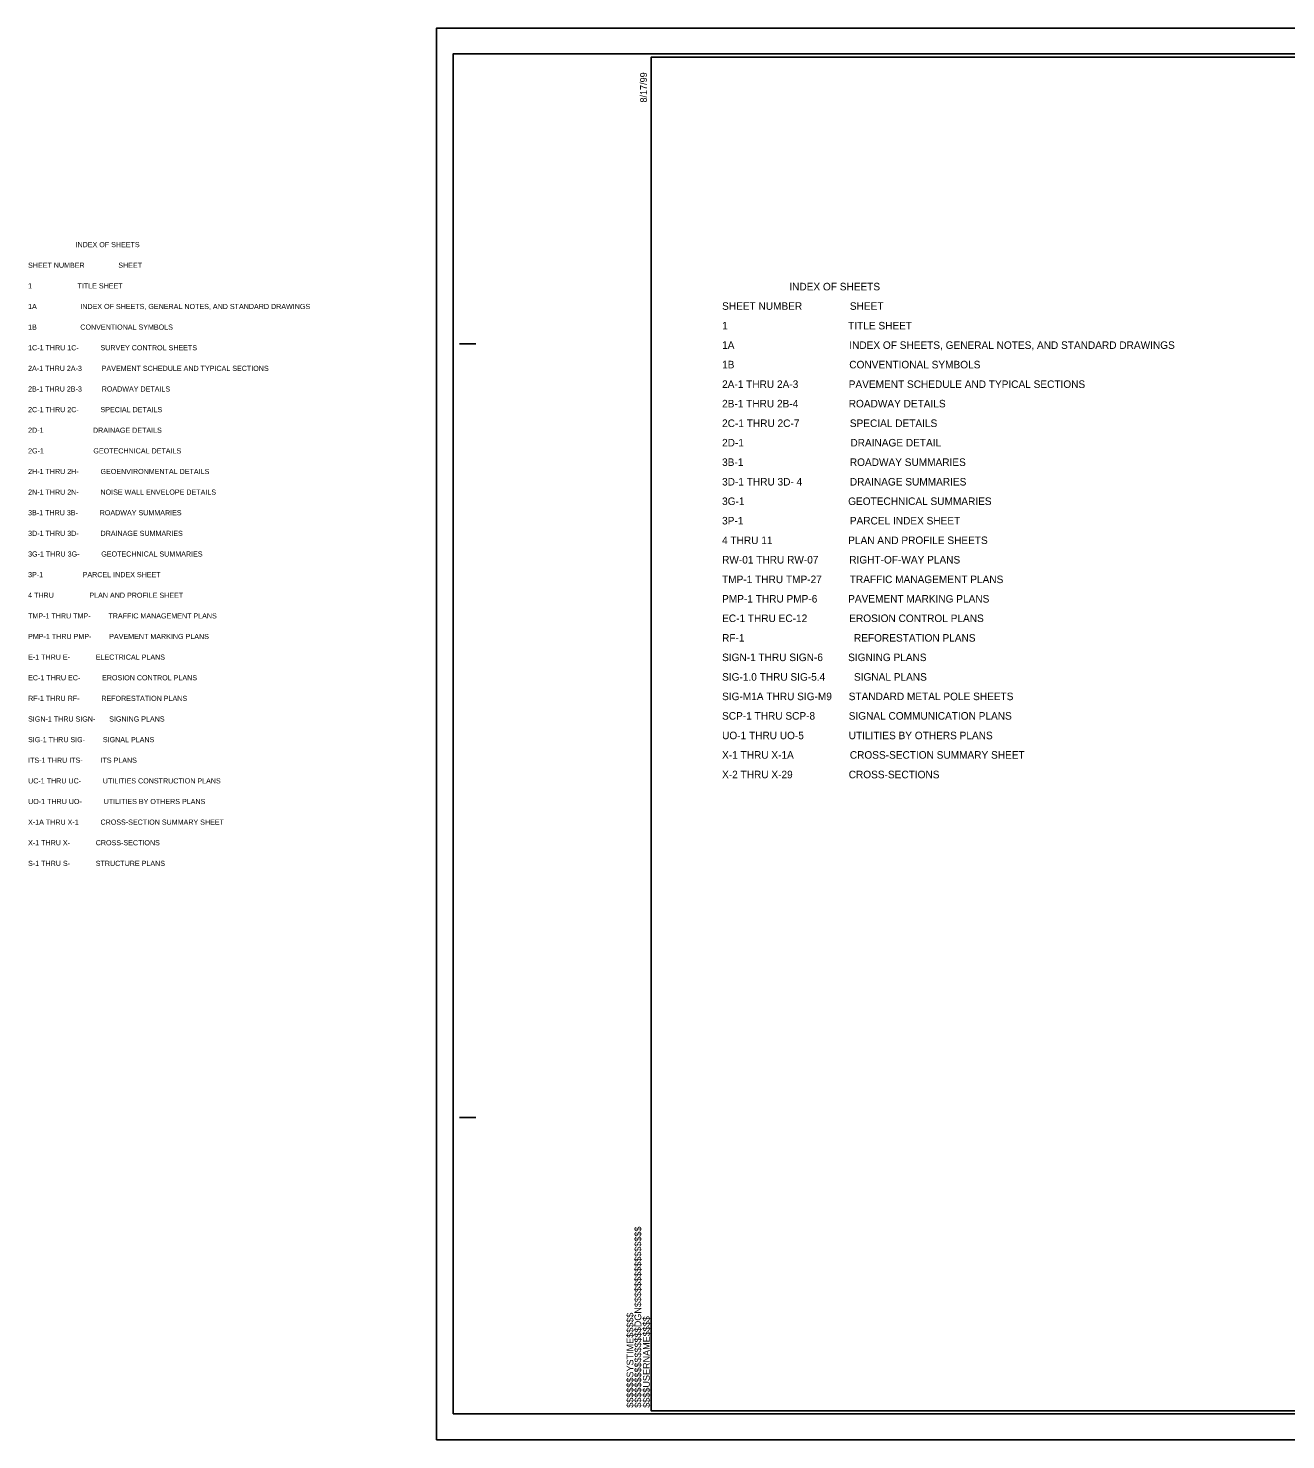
# Model space of a CAD drawing. Extents: x 3312684 to 3314684, y -677777 to -676682.
# Drawn here: x 3312684 to 3313659, y -677777 to -676682 of the extents above; entities that cross this region are included whole.
import ezdxf

# ---------------------------------------------------------------- set-up
doc = ezdxf.new("R2010")
doc.units = 0
for name, color, linetype in [('Sheet Data Text CELL', 7, 'Continuous'), ('Sheet Plan CELL', 7, 'Continuous'), ('Sheet Plot Border Inside CELL', 7, 'Continuous'), ('Sheet Plot Border Outside CELL', 7, 'Continuous')]:
    doc.layers.add(name, color=color, linetype=linetype)

msp = doc.modelspace()

# ---------------------------------------------------------------- linework, layer by layer
at = {"layer": 'Sheet Plan CELL'}
for p, q in [((3313166.7, -676704.5), (3313166.7, -676704.5)), ((3313018.2, -676927), (3313030.7, -676927)), ((3313018.2, -677527), (3313030.7, -677527)), ((3313166.7, -677754.5), (3313166.7, -677754.5))]:
    msp.add_line(p, q, dxfattribs=at)
msp.add_lwpolyline([(3314666.7, -676704.5), (3313166.7, -676704.5), (3313166.7, -677754.5), (3314666.7, -677754.5)], close=True, dxfattribs=at)
at = {"layer": 'Sheet Plot Border Inside CELL'}
msp.add_lwpolyline([(3313013.2, -677757), (3314679.2, -677757), (3314679.2, -676702), (3313013.2, -676702)], close=True, dxfattribs=at)
at = {"layer": 'Sheet Plot Border Outside CELL'}
msp.add_lwpolyline([(3313000.2, -677777), (3314683.7, -677777), (3314683.7, -676682), (3313000.2, -676682)], close=True, dxfattribs=at)

# ---------------------------------------------------------------- texts
at = {"layer": 'Sheet Data Text CELL'}
for s, height, p in [('                        INDEX OF SHEETS ', 4, (3312683.5, -676851.9)), ('SHEET NUMBER                 SHEET   ', 4, (3312683.5, -676867.9)), ('1                       TITLE SHEET', 4, (3312683.5, -676883.9)), ('                        INDEX OF SHEETS ', 5.849, (3313221.8, -676885.4)), ('1A                      INDEX OF SHEETS, GENERAL NOTES, AND STANDARD DRAWINGS', 4, (3312683.5, -676899.9)), ('SHEET NUMBER                 SHEET   ', 5.849, (3313221.8, -676900.5)), ('1B                      CONVENTIONAL SYMBOLS ', 4, (3312683.5, -676915.9)), ('1                                           TITLE SHEET', 5.849, (3313221.8, -676915.7)), ('1C-1 THRU 1C-           SURVEY CONTROL SHEETS', 4, (3312683.5, -676931.9)), ('1A                                         INDEX OF SHEETS, GENERAL NOTES, AND STANDARD DRAWINGS', 5.849, (3313221.8, -676930.8)), ('2A-1 THRU 2A-3          PAVEMENT SCHEDULE AND TYPICAL SECTIONS', 4, (3312683.5, -676947.9)), ('1B                                         CONVENTIONAL SYMBOLS ', 5.849, (3313221.8, -676945.9)), ('2B-1 THRU 2B-3          ROADWAY DETAILS ', 4, (3312683.5, -676963.9)), ('2A-1 THRU 2A-3                  PAVEMENT SCHEDULE AND TYPICAL SECTIONS', 5.849, (3313221.8, -676961.1)), ('2B-1 THRU 2B-4                  ROADWAY DETAILS ', 5.849, (3313221.8, -676976.2)), ('2C-1 THRU 2C-           SPECIAL DETAILS', 4, (3312683.5, -676979.9)), ('2D-1                         DRAINAGE DETAILS', 4, (3312683.5, -676995.9)), ('2C-1 THRU 2C-7                  SPECIAL DETAILS', 5.849, (3313221.8, -676991.4)), ('2D-1                                      DRAINAGE DETAIL', 5.849, (3313221.8, -677006.5)), ('2G-1                         GEOTECHNICAL DETAILS', 4, (3312683.5, -677011.9)), ('3B-1                                      ROADWAY SUMMARIES', 5.849, (3313221.8, -677021.6)), ('2H-1 THRU 2H-           GEOENVIRONMENTAL DETAILS', 4, (3312683.5, -677027.9)), ('3D-1 THRU 3D- 4                 DRAINAGE SUMMARIES', 5.849, (3313221.8, -677036.8)), ('2N-1 THRU 2N-           NOISE WALL ENVELOPE DETAILS', 4, (3312683.5, -677043.9)), ('3G-1                                     GEOTECHNICAL SUMMARIES', 5.849, (3313221.8, -677051.9)), ('3B-1 THRU 3B-           ROADWAY SUMMARIES', 4, (3312683.5, -677059.9)), ('3P-1                                      PARCEL INDEX SHEET', 5.849, (3313221.8, -677067)), ('3D-1 THRU 3D-           DRAINAGE SUMMARIES', 4, (3312683.5, -677075.9)), ('4 THRU 11                           PLAN AND PROFILE SHEETS', 5.849, (3313221.8, -677082.2)), ('3G-1 THRU 3G-           GEOTECHNICAL SUMMARIES', 4, (3312683.5, -677091.9)), ('RW-01 THRU RW-07           RIGHT-OF-WAY PLANS', 5.849, (3313221.8, -677097.3)), ('3P-1                    PARCEL INDEX SHEET', 4, (3312683.5, -677107.9)), ('TMP-1 THRU TMP-27          TRAFFIC MANAGEMENT PLANS', 5.849, (3313221.8, -677112.5)), ('4 THRU                  PLAN AND PROFILE SHEET', 4, (3312683.5, -677123.9)), ('PMP-1 THRU PMP-6           PAVEMENT MARKING PLANS', 5.849, (3313221.8, -677127.6)), ('TMP-1 THRU TMP-         TRAFFIC MANAGEMENT PLANS', 4, (3312683.5, -677139.9)), ('EC-1 THRU EC-12               EROSION CONTROL PLANS', 5.849, (3313221.8, -677142.7)), ('PMP-1 THRU PMP-         PAVEMENT MARKING PLANS', 4, (3312683.5, -677155.9)), ('RF-1', 5.85, (3313221.8, -677157.9)), ('    REFORESTATION PLANS', 5.849, (3313315.4, -677157.9)), ('E-1 THRU E-             ELECTRICAL PLANS', 4, (3312683.5, -677171.9)), ('SIGN-1 THRU SIGN-6         SIGNING PLANS', 5.849, (3313221.8, -677173)), ('EC-1 THRU EC-           EROSION CONTROL PLANS', 4, (3312683.5, -677187.9)), ('SIG-1.0 THRU SIG-5.4', 5.849, (3313221.8, -677188.2)), ('    SIGNAL PLANS', 5.849, (3313315.4, -677188.2)), ('RF-1 THRU RF-           REFORESTATION PLANS', 4, (3312683.5, -677203.9)), ('SIG-M1A THRU SIG-M9      STANDARD METAL POLE SHEETS', 5.849, (3313221.8, -677203.3)), ('SCP-1 THRU SCP-8            SIGNAL COMMUNICATION PLANS', 5.849, (3313221.8, -677218.4)), ('SIGN-1 THRU SIGN-       SIGNING PLANS', 4, (3312683.5, -677219.9)), ('SIG-1 THRU SIG-         SIGNAL PLANS', 4, (3312683.5, -677235.9)), ('UO-1 THRU UO-5                UTILITIES BY OTHERS PLANS', 5.849, (3313221.8, -677233.6)), ('X-1 THRU X-1A                    CROSS-SECTION SUMMARY SHEET', 5.849, (3313221.8, -677248.7)), ('ITS-1 THRU ITS-         ITS PLANS', 4, (3312683.5, -677251.9)), ('UC-1 THRU UC-           UTILITIES CONSTRUCTION PLANS', 4, (3312683.5, -677267.9)), ('X-2 THRU X-29                    CROSS-SECTIONS', 5.849, (3313221.8, -677263.9)), ('UO-1 THRU UO-           UTILITIES BY OTHERS PLANS', 4, (3312683.5, -677283.9)), ('X-1A THRU X-1           CROSS-SECTION SUMMARY SHEET', 4, (3312683.5, -677299.9)), ('X-1 THRU X-             CROSS-SECTIONS', 4, (3312683.5, -677315.9)), ('S-1 THRU S-             STRUCTURE PLANS', 4, (3312683.5, -677331.9))]:
    msp.add_text(s, height=height, dxfattribs=at).set_placement(p)
at = {"layer": 'Sheet Plan CELL'}
for s, p in [('8/17/99', (3313163.5, -676739.7)), ('$$$$$$$$$$$$$$$$DGN$$$$$$$$$$$$$$$$', (3313159.1, -677752.2)), ('$$$$$$SYSTIME$$$$$', (3313153, -677752.2)), ('$$$$USERNAME$$$$', (3313165.7, -677752.2))]:
    msp.add_text(s, height=5.25, rotation=90, dxfattribs=at).set_placement(p)

doc.saveas('drawing.dxf')
